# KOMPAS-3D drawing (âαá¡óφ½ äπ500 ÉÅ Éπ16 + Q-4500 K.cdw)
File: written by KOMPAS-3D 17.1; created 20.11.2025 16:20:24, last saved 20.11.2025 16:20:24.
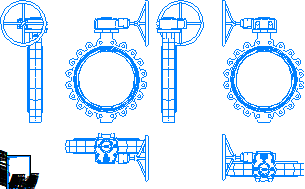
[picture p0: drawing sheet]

Sheet 1: A4, portrait

Title block, sheet 1: material: Сталь 20  ГОСТ 1050-2013; mass: 212,72; sheets: 1; sheet format: A4

Views: Проекционный вид 3, Проекционный вид 4, Проекционный вид 6
Referenced files in \\adlc.lan\data\АДЛ_ПКД\3D-модели\ADL production\Дисковые поворотные затворы ГРАНВЭЛ\с резьбовыми проушинами с китайским редуктором Ру 16\KOMPAS 3D\: Гранвэл Ду500 РП Ру16 + Q-4500 K.m3d
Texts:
  Andrey
  АДЛ
Dimensions and other numbers on the sheet: 1:1; 1; 212,72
